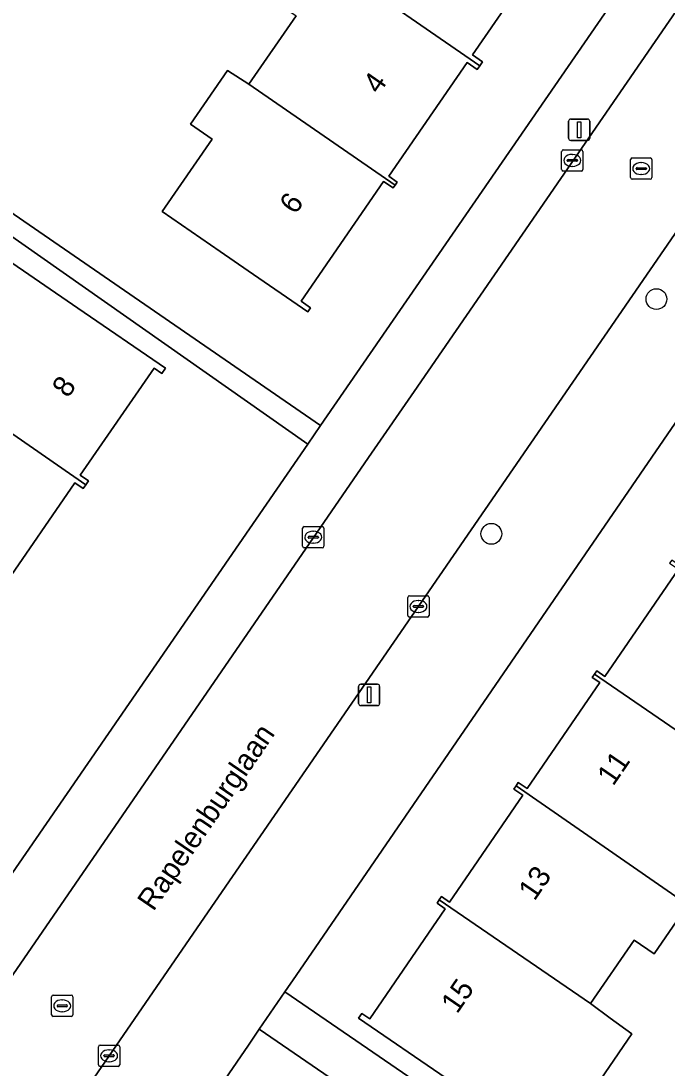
# Model space of a CAD drawing. Extents: x 160157 to 160921, y 381516 to 382045.
# Drawn here: x 160661.83 to 160692.23, y 381759.62 to 381808.91 of the extents above; entities that cross this region are included whole.
import ezdxf

# ---------------------------------------------------------------- set-up
doc = ezdxf.new("R2010")
doc.units = 0
for name, color, linetype in [('IMGEO_Boom', 7, 'Continuous'), ('IMGEO_Erf', 7, 'Continuous'), ('IMGEO_Kolk', 7, 'Continuous'), ('IMGEO_Lichtmast', 7, 'Continuous'), ('IMGEO_Openbare_ruimte_label', 7, 'Continuous'), ('IMGEO_Pand', 7, 'Continuous'), ('IMGEO_Pand_nummerreeks', 7, 'Continuous'), ('IMGEO_Rijbaan_lokaal_open', 7, 'Continuous'), ('IMGEO_Rioolput', 7, 'Continuous'), ('IMGEO_Voetpad_open', 7, 'Continuous')]:
    doc.layers.add(name, color=color, linetype=linetype)

msp = doc.modelspace()

# ---------------------------------------------------------------- linework, layer by layer
at = {"layer": 'IMGEO_Boom'}
for centre in [(160691.734, 381795.815), (160683.969, 381784.767)]:
    msp.add_circle(centre, 0.489, dxfattribs=at)
at = {"layer": 'IMGEO_Erf'}
for points in [[(160651.567, 381806.643), (160675.928, 381789.86), (160692.079, 381813.304), (160676.409, 381824.1), (160673.783, 381820.397), (160667.957, 381824.529), (160668.528, 381825.335), (160666.692, 381826.637), (160668.746, 381829.534)], [(160686.795, 381812.701), (160683.076, 381807.306), (160683.552, 381806.978), (160683.43, 381806.8), (160683.307, 381806.621), (160682.831, 381806.949), (160679.14, 381801.595), (160679.537, 381801.322), (160679.442, 381801.183), (160679.348, 381801.047), (160678.901, 381801.355), (160675.013, 381795.714), (160675.459, 381795.407), (160675.328, 381795.216), (160672.528, 381797.146), (160671.212, 381798.054), (160668.478, 381799.938), (160670.827, 381803.346), (160669.811, 381804.046), (160671.556, 381806.578), (160672.564, 381805.927), (160674.782, 381809.143)], [(160704.201, 381806.878), (160674.789, 381763.984), (160674.255, 381763.205), (160683.384, 381756.947)], [(160648.467, 381750), (160675.328, 381788.989), (160654.242, 381803.777)], [(160660.906, 381797.872), (160664.512, 381795.392), (160668.631, 381792.558), (160668.466, 381792.319), (160668.101, 381792.57), (160664.628, 381787.522), (160665.013, 381787.257), (160664.888, 381787.076), (160664.763, 381786.894), (160664.373, 381787.162), (160661.034, 381782.308)], [(160681.842, 381759.148), (160677.718, 381761.975), (160677.871, 381762.199), (160678.246, 381761.942), (160681.799, 381767.123), (160681.413, 381767.388), (160681.518, 381767.542), (160681.622, 381767.694), (160682.003, 381767.432), (160685.454, 381772.465), (160685.029, 381772.756), (160685.131, 381772.905), (160685.235, 381773.057), (160685.647, 381772.775), (160689.068, 381777.765), (160688.715, 381778.007), (160688.819, 381778.159), (160688.925, 381778.312), (160689.306, 381778.051), (160692.767, 381783.099)], [(160693.214, 381767.308), (160691.629, 381764.996), (160690.682, 381765.646), (160688.635, 381762.661), (160689.564, 381761.979), (160690.583, 381761.231), (160686.816, 381755.737)], [(160690.156, 381749.722), (160673.051, 381761.449), (160672.541, 381760.705), (160665.2, 381750)]]:
    msp.add_lwpolyline(points, dxfattribs=at)
at = {"layer": 'IMGEO_Kolk'}
for p, q in [((160687.276, 381801.916), (160687.276, 381802.768)), ((160687.351, 381802.842), (160688.203, 381802.842)), ((160688.277, 381802.768), (160688.277, 381801.916)), ((160687.535, 381802.336), (160687.535, 381802.348)), ((160687.973, 381802.299), (160687.575, 381802.299)), ((160687.578, 381802.385), (160687.976, 381802.385)), ((160687.764, 381802.622), (160687.789, 381802.622)), ((160688.019, 381802.348), (160688.019, 381802.336)), ((160688.203, 381801.842), (160687.351, 381801.842)), ((160687.787, 381802.062), (160687.762, 381802.062)), ((160675.087, 381784.181), (160675.087, 381785.033)), ((160675.162, 381785.107), (160676.014, 381785.107)), ((160676.088, 381785.033), (160676.088, 381784.181)), ((160675.346, 381784.601), (160675.346, 381784.613)), ((160675.784, 381784.564), (160675.386, 381784.564)), ((160675.389, 381784.65), (160675.787, 381784.65)), ((160675.575, 381784.887), (160675.6, 381784.887)), ((160675.83, 381784.613), (160675.83, 381784.601)), ((160676.014, 381784.107), (160675.162, 381784.107)), ((160675.598, 381784.327), (160675.573, 381784.327)), ((160680.036, 381780.925), (160680.036, 381781.777)), ((160680.111, 381781.851), (160680.963, 381781.851)), ((160680.524, 381781.631), (160680.549, 381781.631)), ((160681.037, 381781.777), (160681.037, 381780.925)), ((160680.295, 381781.345), (160680.295, 381781.357)), ((160680.733, 381781.308), (160680.335, 381781.308)), ((160680.338, 381781.394), (160680.736, 381781.394)), ((160680.779, 381781.357), (160680.779, 381781.345)), ((160680.963, 381780.851), (160680.111, 381780.851)), ((160680.547, 381781.071), (160680.522, 381781.071)), ((160665.482, 381759.777), (160665.482, 381760.629)), ((160665.557, 381760.703), (160666.409, 381760.703)), ((160665.97, 381760.483), (160665.995, 381760.483)), ((160666.483, 381760.629), (160666.483, 381759.777)), ((160665.741, 381760.197), (160665.741, 381760.209)), ((160666.179, 381760.16), (160665.781, 381760.16)), ((160665.784, 381760.246), (160666.182, 381760.246)), ((160665.993, 381759.923), (160665.968, 381759.923)), ((160666.225, 381760.209), (160666.225, 381760.197)), ((160666.409, 381759.703), (160665.557, 381759.703))]:
    msp.add_line(p, q, dxfattribs=at)
for points in [[(160687.276, 381801.916), (160687.276, 381802.768)], [(160687.351, 381802.842), (160688.203, 381802.842)], [(160688.277, 381802.768), (160688.277, 381801.916)], [(160688.203, 381801.842), (160687.351, 381801.842)], [(160675.087, 381784.181), (160675.087, 381785.033)], [(160675.162, 381785.107), (160676.014, 381785.107)], [(160676.088, 381785.033), (160676.088, 381784.181)], [(160676.014, 381784.107), (160675.162, 381784.107)], [(160680.036, 381780.925), (160680.036, 381781.777)], [(160680.111, 381781.851), (160680.963, 381781.851)], [(160681.037, 381781.777), (160681.037, 381780.925)], [(160680.963, 381780.851), (160680.111, 381780.851)], [(160665.482, 381759.777), (160665.482, 381760.629)], [(160665.557, 381760.703), (160666.409, 381760.703)], [(160666.483, 381760.629), (160666.483, 381759.777)], [(160666.409, 381759.703), (160665.557, 381759.703)]]:
    msp.add_lwpolyline(points, dxfattribs=at)
for centre, radius, start, end in [((160687.353, 381802.766), 0.0765, 91.552, 178.448), ((160687.353, 381802.766), 0.0765, 91.552, 178.448), ((160688.201, 381802.766), 0.0765, 1.552, 88.448), ((160688.201, 381802.766), 0.0765, 1.552, 88.448), ((160687.575, 381802.345), 0.0403, 85.8775, 175.7526), ((160687.572, 381802.335), 0.0366, 178.938, 274.7102), ((160687.976, 381802.342), 0.043, 264.8664, 352.4533), ((160687.98, 381802.347), 0.0386, 1.7309, 96.639), ((160687.353, 381801.918), 0.0765, 181.552, 268.448), ((160687.353, 381801.918), 0.0765, 181.552, 268.448), ((160688.201, 381801.918), 0.0765, 271.552, 358.448), ((160688.201, 381801.918), 0.0765, 271.552, 358.448), ((160675.164, 381785.031), 0.0765, 91.552, 178.448), ((160675.164, 381785.031), 0.0765, 91.552, 178.448), ((160676.012, 381785.031), 0.0765, 1.552, 88.448), ((160676.012, 381785.031), 0.0765, 1.552, 88.448), ((160675.386, 381784.61), 0.0403, 85.8775, 175.7526), ((160675.383, 381784.6), 0.0366, 178.938, 274.7102), ((160675.787, 381784.607), 0.043, 264.8664, 352.4533), ((160675.791, 381784.612), 0.0386, 1.7309, 96.639), ((160675.164, 381784.183), 0.0765, 181.552, 268.448), ((160675.164, 381784.183), 0.0765, 181.552, 268.448), ((160676.012, 381784.183), 0.0765, 271.552, 358.448), ((160676.012, 381784.183), 0.0765, 271.552, 358.448), ((160680.113, 381781.775), 0.0765, 91.552, 178.448), ((160680.113, 381781.775), 0.0765, 91.552, 178.448), ((160680.961, 381781.775), 0.0765, 1.552, 88.448), ((160680.961, 381781.775), 0.0765, 1.552, 88.448), ((160680.335, 381781.354), 0.0403, 85.8775, 175.7526), ((160680.332, 381781.344), 0.0366, 178.938, 274.7102), ((160680.736, 381781.351), 0.043, 264.8664, 352.4533), ((160680.74, 381781.356), 0.0386, 1.7309, 96.639), ((160680.113, 381780.927), 0.0765, 181.552, 268.448), ((160680.113, 381780.927), 0.0765, 181.552, 268.448), ((160680.961, 381780.927), 0.0765, 271.552, 358.448), ((160680.961, 381780.927), 0.0765, 271.552, 358.448), ((160665.559, 381760.627), 0.0765, 91.552, 178.448), ((160665.559, 381760.627), 0.0765, 91.552, 178.448), ((160666.407, 381760.627), 0.0765, 1.552, 88.448), ((160666.407, 381760.627), 0.0765, 1.552, 88.448), ((160665.781, 381760.206), 0.0403, 85.8775, 175.7526), ((160665.778, 381760.196), 0.0366, 178.938, 274.7102), ((160666.182, 381760.203), 0.043, 264.8664, 352.4533), ((160666.186, 381760.208), 0.0386, 1.7309, 96.639), ((160665.559, 381759.779), 0.0765, 181.552, 268.448), ((160665.559, 381759.779), 0.0765, 181.552, 268.448), ((160666.407, 381759.779), 0.0765, 271.552, 358.448), ((160666.407, 381759.779), 0.0765, 271.552, 358.448)]:
    msp.add_arc(centre, radius, start, end, dxfattribs=at)
for centre, major_axis, ratio, start_param, end_param in [((160687.763, 381802.342), (-0.387, 0.002), 0.722429, 4.712389, 7.853982), ((160687.788, 381802.342), (-0.39, 0.002), 0.717154, 1.570796, 4.712389), ((160675.574, 381784.607), (-0.387, 0.002), 0.722429, 4.712389, 7.853982), ((160675.599, 381784.607), (-0.39, 0.002), 0.717154, 1.570796, 4.712389), ((160680.523, 381781.351), (-0.387, 0.002), 0.722429, 4.712389, 7.853982), ((160680.548, 381781.351), (-0.39, 0.002), 0.717154, 1.570796, 4.712389), ((160665.969, 381760.203), (-0.387, 0.002), 0.722429, 4.712389, 7.853982), ((160665.994, 381760.203), (-0.39, 0.002), 0.717154, 1.570796, 4.712389)]:
    msp.add_ellipse(centre, major_axis=major_axis, ratio=ratio, start_param=start_param, end_param=end_param, dxfattribs=at)
at = {"layer": 'IMGEO_Lichtmast'}
for p, q in [((160687.704, 381804.286), (160688.494, 381804.286)), ((160688.494, 381804.286), (160687.704, 381804.286)), ((160687.604, 381803.386), (160687.604, 381804.186)), ((160687.604, 381804.186), (160687.604, 381803.386)), ((160688.594, 381804.186), (160688.594, 381803.386)), ((160688.594, 381803.386), (160688.594, 381804.186)), ((160688.494, 381803.286), (160687.704, 381803.286)), ((160687.704, 381803.286), (160688.494, 381803.286)), ((160677.822, 381777.686), (160678.612, 381777.686)), ((160678.612, 381777.686), (160677.822, 381777.686)), ((160677.722, 381776.786), (160677.722, 381777.586)), ((160677.722, 381777.586), (160677.722, 381776.786)), ((160678.712, 381777.586), (160678.712, 381776.786)), ((160678.712, 381776.786), (160678.712, 381777.586)), ((160678.612, 381776.686), (160677.822, 381776.686)), ((160677.822, 381776.686), (160678.612, 381776.686))]:
    msp.add_line(p, q, dxfattribs=at)
for points in [[(160688.024, 381804.161), (160688.174, 381804.161), (160688.174, 381803.411), (160688.024, 381803.411), (160688.024, 381804.161)], [(160678.142, 381777.561), (160678.292, 381777.561), (160678.292, 381776.811), (160678.142, 381776.811), (160678.142, 381777.561)]]:
    msp.add_lwpolyline(points, dxfattribs=at)
for centre, start, end in [((160687.704, 381804.186), 90, 180), ((160687.704, 381804.186), 90, 180), ((160688.494, 381804.186), 0, 90), ((160688.494, 381804.186), 360, 90), ((160687.704, 381803.386), 180, 270), ((160687.704, 381803.386), 180, 270), ((160688.494, 381803.386), 270, 0), ((160688.494, 381803.386), 270, 0), ((160677.822, 381777.586), 90, 180), ((160677.822, 381777.586), 90, 180), ((160678.612, 381777.586), 0, 90), ((160678.612, 381777.586), 360, 90), ((160677.822, 381776.786), 180, 270), ((160677.822, 381776.786), 180, 270), ((160678.612, 381776.786), 270, 0), ((160678.612, 381776.786), 270, 0)]:
    msp.add_arc(centre, 0.1, start, end, dxfattribs=at)
at = {"layer": 'IMGEO_Pand'}
for points in [[(160683.308, 381815.523), (160682.279, 381816.233), (160683.504, 381818.011), (160680.755, 381819.906), (160680.448, 381820.118), (160677.621, 381816.017), (160677.226, 381816.289), (160674.793, 381812.761), (160675.497, 381812.275), (160676.513, 381811.574), (160683.43, 381806.8), (160683.552, 381806.978), (160683.076, 381807.306), (160686.795, 381812.701), (160687.229, 381812.402), (160687.425, 381812.686)], [(160676.513, 381811.574), (160675.497, 381812.275), (160674.793, 381812.761), (160673.072, 381810.264), (160673.803, 381809.818), (160674.782, 381809.143), (160672.564, 381805.927), (160679.442, 381801.183), (160679.537, 381801.322), (160679.14, 381801.595), (160682.831, 381806.949), (160683.307, 381806.621), (160683.43, 381806.8)], [(160679.442, 381801.183), (160672.564, 381805.927), (160671.556, 381806.578), (160669.811, 381804.046), (160670.827, 381803.346), (160668.478, 381799.938), (160671.212, 381798.054), (160672.528, 381797.146), (160675.328, 381795.216), (160675.459, 381795.407), (160675.013, 381795.714), (160678.901, 381801.355), (160679.348, 381801.047)], [(160657.351, 381792.288), (160657.842, 381791.95), (160664.888, 381787.076), (160665.013, 381787.257), (160664.628, 381787.522), (160668.101, 381792.57), (160668.466, 381792.319), (160668.631, 381792.558), (160664.512, 381795.392), (160660.906, 381797.872), (160659.263, 381795.483), (160657.645, 381795.057), (160657.127, 381794.303)], [(160657.842, 381791.95), (160657.351, 381792.288), (160657.037, 381792.504), (160655.446, 381790.191), (160654.935, 381789.448), (160653.428, 381787.258), (160654.242, 381786.699), (160661.233, 381781.879), (160661.369, 381782.077), (160661.034, 381782.308), (160664.373, 381787.162), (160664.763, 381786.894), (160664.888, 381787.076)], [(160688.819, 381778.159), (160695.912, 381773.294), (160697.988, 381776.322), (160698.926, 381775.679), (160700.499, 381777.973), (160699.549, 381778.667), (160692.453, 381783.534), (160692.351, 381783.385), (160692.767, 381783.099), (160689.306, 381778.051), (160688.925, 381778.312)], [(160685.131, 381772.905), (160693.214, 381767.308), (160694.13, 381766.627), (160697.757, 381771.914), (160696.84, 381772.6), (160695.912, 381773.294), (160688.819, 381778.159), (160688.715, 381778.007), (160689.068, 381777.765), (160685.647, 381772.775), (160685.235, 381773.057)], [(160685.131, 381772.905), (160685.029, 381772.756), (160685.454, 381772.465), (160682.003, 381767.432), (160681.622, 381767.694), (160681.518, 381767.542), (160688.635, 381762.661), (160690.682, 381765.646), (160691.629, 381764.996), (160693.214, 381767.308)], [(160689.564, 381761.979), (160688.635, 381762.661), (160681.518, 381767.542), (160681.413, 381767.388), (160681.799, 381767.123), (160678.246, 381761.942), (160677.871, 381762.199), (160677.718, 381761.975), (160681.842, 381759.148), (160683.917, 381757.725), (160684.779, 381757.134), (160686.816, 381755.737), (160690.583, 381761.231)]]:
    msp.add_lwpolyline(points, close=True, dxfattribs=at)
at = {"layer": 'IMGEO_Rijbaan_lokaal_open'}
msp.add_lwpolyline([(160658.96, 381750), (160667.503, 381762.414), (160670.296, 381766.471), (160700.524, 381810.394), (160703.573, 381814.824), (160712.504, 381827.801), (160716.028, 381832.837), (160716.089, 381833.009), (160711.248, 381836.325), (160711.08, 381836.076), (160707.501, 381830.956), (160699.651, 381819.545), (160692.328, 381808.901), (160680.332, 381791.464), (160678.334, 381788.56), (160651.806, 381750)], dxfattribs=at)
at = {"layer": 'IMGEO_Rioolput'}
for p, q in [((160690.519, 381801.531), (160690.519, 381802.383)), ((160690.594, 381802.457), (160691.446, 381802.457)), ((160691.52, 381802.383), (160691.52, 381801.531)), ((160690.778, 381801.951), (160690.778, 381801.963)), ((160691.216, 381801.914), (160690.818, 381801.914)), ((160690.821, 381802), (160691.219, 381802)), ((160691.007, 381802.237), (160691.032, 381802.237)), ((160691.262, 381801.963), (160691.262, 381801.951)), ((160691.446, 381801.457), (160690.594, 381801.457)), ((160691.03, 381801.677), (160691.005, 381801.677)), ((160663.276, 381762.128), (160663.276, 381762.98)), ((160663.351, 381763.054), (160664.203, 381763.054)), ((160664.277, 381762.98), (160664.277, 381762.128)), ((160663.535, 381762.548), (160663.535, 381762.56)), ((160663.973, 381762.511), (160663.575, 381762.511)), ((160663.578, 381762.597), (160663.976, 381762.597)), ((160663.764, 381762.834), (160663.789, 381762.834)), ((160664.019, 381762.56), (160664.019, 381762.548)), ((160664.203, 381762.054), (160663.351, 381762.054)), ((160663.787, 381762.274), (160663.762, 381762.274))]:
    msp.add_line(p, q, dxfattribs=at)
for points in [[(160690.519, 381801.531), (160690.519, 381802.383)], [(160690.594, 381802.457), (160691.446, 381802.457)], [(160691.52, 381802.383), (160691.52, 381801.531)], [(160691.446, 381801.457), (160690.594, 381801.457)], [(160663.276, 381762.128), (160663.276, 381762.98)], [(160663.351, 381763.054), (160664.203, 381763.054)], [(160664.277, 381762.98), (160664.277, 381762.128)], [(160664.203, 381762.054), (160663.351, 381762.054)]]:
    msp.add_lwpolyline(points, dxfattribs=at)
for centre, radius, start, end in [((160690.596, 381802.381), 0.0765, 91.552, 178.448), ((160690.596, 381802.381), 0.0765, 91.552, 178.448), ((160691.444, 381802.381), 0.0765, 1.552, 88.448), ((160691.444, 381802.381), 0.0765, 1.552, 88.448), ((160690.818, 381801.96), 0.0403, 85.8775, 175.7526), ((160690.815, 381801.95), 0.0366, 178.938, 274.7102), ((160691.219, 381801.957), 0.043, 264.8664, 352.4533), ((160691.223, 381801.962), 0.0386, 1.7309, 96.639), ((160690.596, 381801.533), 0.0765, 181.552, 268.448), ((160690.596, 381801.533), 0.0765, 181.552, 268.448), ((160691.444, 381801.533), 0.0765, 271.552, 358.448), ((160691.444, 381801.533), 0.0765, 271.552, 358.448), ((160663.353, 381762.978), 0.0765, 91.552, 178.448), ((160663.353, 381762.978), 0.0765, 91.552, 178.448), ((160664.201, 381762.978), 0.0765, 1.552, 88.448), ((160664.201, 381762.978), 0.0765, 1.552, 88.448), ((160663.575, 381762.557), 0.0403, 85.8775, 175.7526), ((160663.572, 381762.547), 0.0366, 178.938, 274.7102), ((160663.976, 381762.554), 0.043, 264.8664, 352.4533), ((160663.98, 381762.559), 0.0386, 1.7309, 96.639), ((160663.353, 381762.13), 0.0765, 181.552, 268.448), ((160663.353, 381762.13), 0.0765, 181.552, 268.448), ((160664.201, 381762.13), 0.0765, 271.552, 358.448), ((160664.201, 381762.13), 0.0765, 271.552, 358.448)]:
    msp.add_arc(centre, radius, start, end, dxfattribs=at)
for centre, major_axis, ratio, start_param, end_param in [((160691.006, 381801.957), (-0.387, 0.002), 0.722429, 4.712389, 7.853982), ((160691.031, 381801.957), (-0.39, 0.002), 0.717154, 1.570796, 4.712389), ((160663.763, 381762.554), (-0.387, 0.002), 0.722429, 4.712389, 7.853982), ((160663.788, 381762.554), (-0.39, 0.002), 0.717154, 1.570796, 4.712389)]:
    msp.add_ellipse(centre, major_axis=major_axis, ratio=ratio, start_param=start_param, end_param=end_param, dxfattribs=at)
at = {"layer": 'IMGEO_Voetpad_open'}
msp.add_lwpolyline([(160707.501, 381830.956), (160711.08, 381836.076), (160711.248, 381836.325), (160707.078, 381835.076), (160693.176, 381814.897), (160692.079, 381813.304), (160675.928, 381789.86), (160675.328, 381788.989), (160648.467, 381750), (160641.671, 381740.128), (160640.592, 381738.561), (160605.905, 381688.17), (160606.806, 381684.4), (160609.452, 381688.229), (160610.996, 381690.462), (160614.441, 381695.549), (160641.13, 381734.448), (160643.136, 381737.367), (160651.806, 381750), (160678.334, 381788.56), (160680.332, 381791.464), (160692.328, 381808.901), (160699.651, 381819.545)], close=True, dxfattribs=at)
for points in [[(160716.089, 381833.009), (160716.028, 381832.837), (160712.504, 381827.801), (160703.573, 381814.824), (160700.524, 381810.394), (160670.296, 381766.471), (160667.503, 381762.414), (160658.96, 381750), (160642.496, 381725.9), (160640.187, 381722.521), (160619.05, 381691.582), (160615.999, 381687.121), (160614.454, 381684.835), (160611.203, 381680.025), (160615.694, 381677.246), (160615.835, 381678.381), (160616.408, 381679.37), (160644.455, 381719.97), (160645.316, 381721.217), (160665.2, 381750)], [(160665.2, 381750), (160672.541, 381760.705), (160673.051, 381761.449), (160674.255, 381763.205), (160674.789, 381763.984), (160704.201, 381806.878), (160705.185, 381808.313), (160719.08, 381828.577)], [(160654.242, 381803.777), (160675.328, 381788.989), (160675.928, 381789.86), (160651.567, 381806.643)], [(160683.384, 381756.947), (160674.255, 381763.205), (160673.051, 381761.449), (160690.156, 381749.722)]]:
    msp.add_lwpolyline(points, dxfattribs=at)

# ---------------------------------------------------------------- texts
at = {"layer": 'IMGEO_Openbare_ruimte_label'}
msp.add_text('Rapelenburglaan', height=1, rotation=55.5948, dxfattribs=at).set_placement((160668.067, 381766.964))
at = {"layer": 'IMGEO_Pand_nummerreeks'}
for s, rotation, p in [('4', 55.256, (160678.677, 381805.417)), ('6', 55.2552, (160674.75, 381799.755)), ('8', 55.5311, (160664.051, 381791.122)), ('11', 55.5882, (160689.699, 381772.859)), ('13', 55.5882, (160685.996, 381767.452)), ('15', 55.5884, (160682.357, 381762.139))]:
    msp.add_text(s, height=1, rotation=rotation, dxfattribs=at).set_placement(p)

doc.saveas('drawing.dxf')
